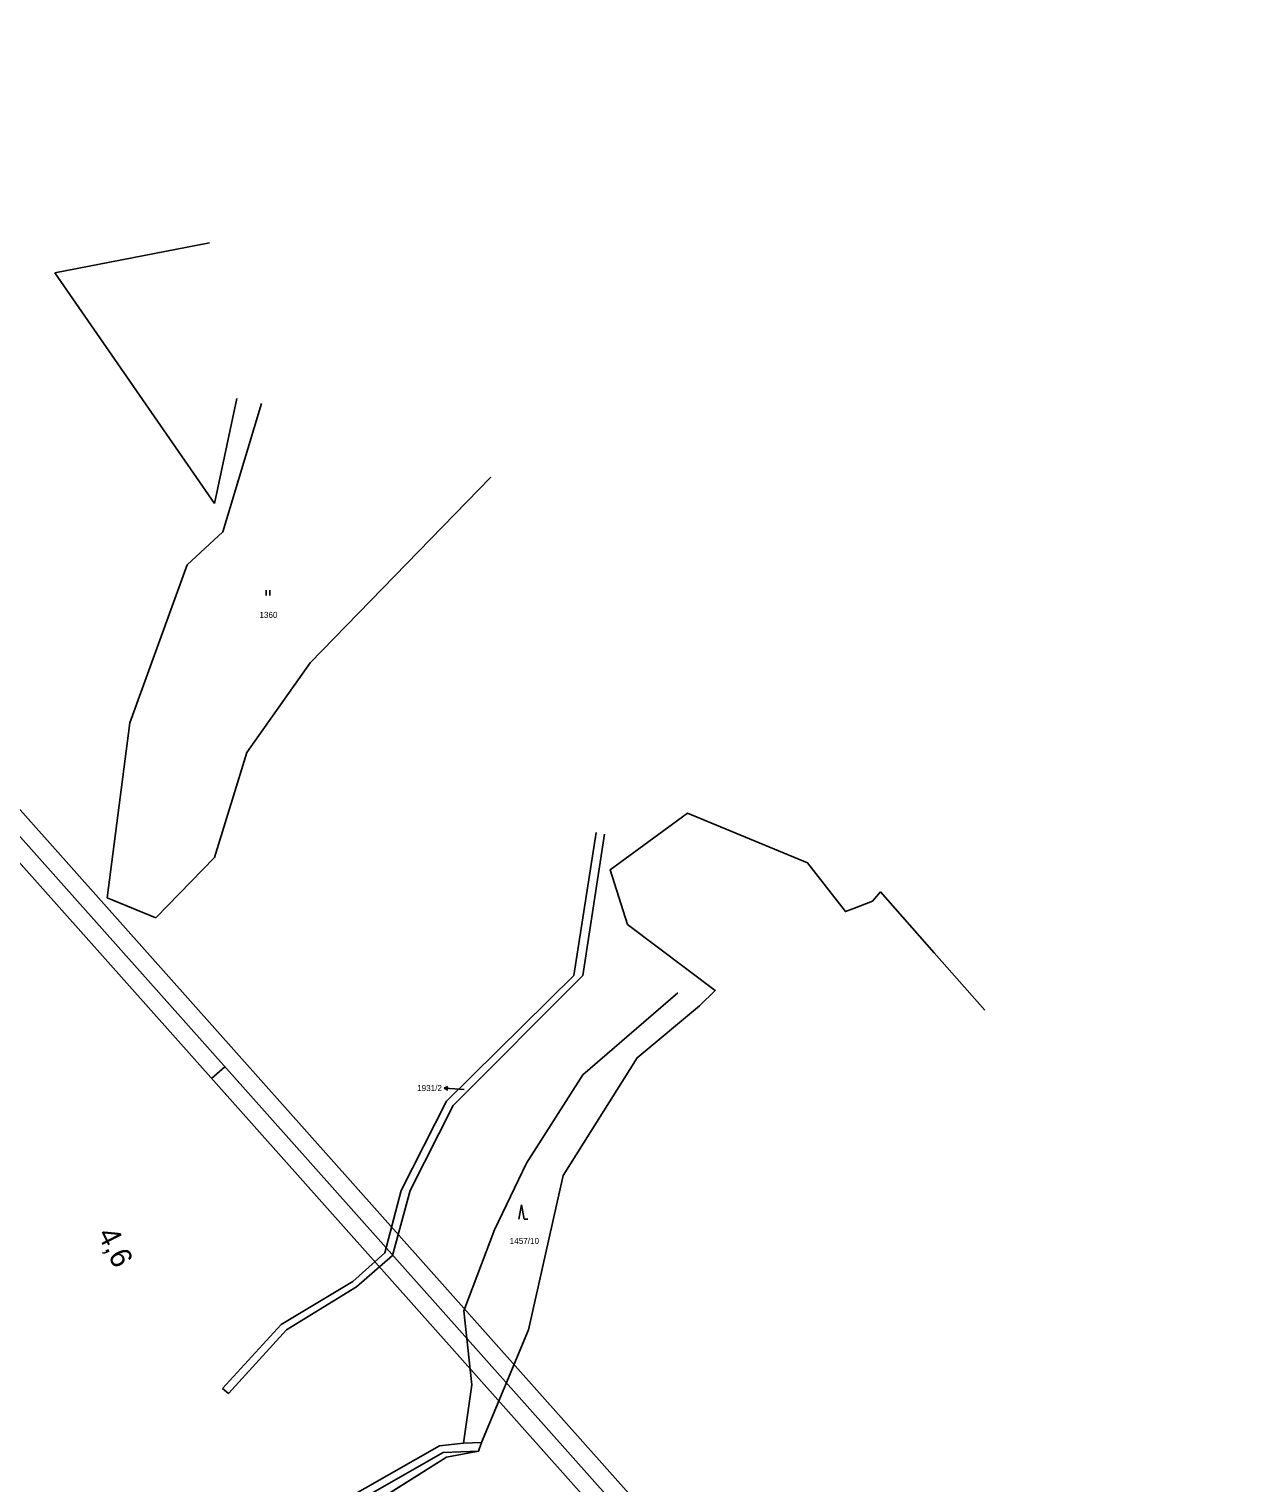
# Model space of a CAD drawing. Extents: x -866656 to -858817, y -1041816 to -1038653.
# Drawn here: x -865010.9 to -864673, y -1040373 to -1039965.6 of the extents above; entities that cross this region are included whole.
import ezdxf

# ---------------------------------------------------------------- set-up
doc = ezdxf.new("R2010")
doc.units = 0
for name, color, linetype in [('Hranice parcel', 7, 'Continuous'), ('Parcelní čísla', 7, 'Continuous'), ('Polygon ku', 7, 'Continuous'), ('Pop  PČ popisy', 7, 'Continuous'), ('tisk ramy', 7, 'Continuous'), ('Vrstva 7', 7, 'Continuous'), ('Značky kultur', 7, 'Continuous')]:
    doc.layers.add(name, color=color, linetype=linetype)

msp = doc.modelspace()

# ---------------------------------------------------------------- linework, layer by layer
at = {"layer": 'Hranice parcel'}
for p, q in [((-864960.28, -1040025.5), (-865003.64, -1040033.94)), ((-865003.64, -1040033.94), (-864958.88, -1040098.54)), ((-864958.88, -1040098.54), (-864952.62, -1040069.15)), ((-864956.54, -1040106.53), (-864945.76, -1040070.56)), ((-864881.51, -1040091.15), (-864932.05, -1040143.17)), ((-864966.57, -1040115.79), (-864956.54, -1040106.53)), ((-864982.65, -1040160.02), (-864966.57, -1040115.79)), ((-864932.05, -1040143.17), (-864949.88, -1040168.33)), ((-864989.01, -1040209.06), (-864982.65, -1040160.02)), ((-864949.88, -1040168.33), (-864958.94, -1040197.78)), ((-864852, -1040190.74), (-864858.23, -1040230.86)), ((-864855.69, -1040230.8), (-864849.66, -1040191.21)), ((-864958.94, -1040197.78), (-864975.36, -1040214.7)), ((-864975.36, -1040214.7), (-864989.01, -1040209.06)), ((-864892.07, -1040267.21), (-864855.69, -1040230.8)), ((-864858.23, -1040230.86), (-864893.89, -1040266)), ((-864855.68, -1040258.63), (-864829.05, -1040235.69)), ((-864840.47, -1040253.86), (-864823.05, -1040239.37)), ((-864861.25, -1040286.85), (-864840.47, -1040253.86)), ((-864871.44, -1040283.43), (-864855.68, -1040258.63)), ((-864893.89, -1040266), (-864906.61, -1040291.09)), ((-864904.04, -1040291.1), (-864892.07, -1040267.21)), ((-864880.43, -1040302.05), (-864871.44, -1040283.43)), ((-864870.94, -1040330.15), (-864861.25, -1040286.85)), ((-864906.61, -1040291.09), (-864911.13, -1040308.53)), ((-864908.98, -1040309.25), (-864904.04, -1040291.1)), ((-864888.99, -1040324.76), (-864880.43, -1040302.05)), ((-864911.13, -1040308.53), (-864920.12, -1040316.54)), ((-864919.1, -1040318.02), (-864908.98, -1040309.25)), ((-864920.12, -1040316.54), (-864940.25, -1040328.64)), ((-864938.71, -1040330.09), (-864919.1, -1040318.02)), ((-864886.78, -1040345.49), (-864888.99, -1040324.76)), ((-864940.25, -1040328.64), (-864956.69, -1040346.6)), ((-864954.99, -1040347.98), (-864938.71, -1040330.09)), ((-864884.09, -1040361.7), (-864870.94, -1040330.15)), ((-864956.69, -1040346.6), (-864954.99, -1040347.98)), ((-864889.09, -1040361.91), (-864886.78, -1040345.49)), ((-864895.84, -1040362.62), (-864947.33, -1040391.83)), ((-864894.83, -1040364.45), (-864946.61, -1040393.97)), ((-864889.09, -1040361.91), (-864895.84, -1040362.62)), ((-864884.92, -1040364.12), (-864894.83, -1040364.45)), ((-864893.92, -1040365.81), (-864884.92, -1040364.12)), ((-864884.09, -1040361.7), (-864889.09, -1040361.91)), ((-864884.92, -1040364.12), (-864884.09, -1040361.7)), ((-864939.01, -1040394.23), (-864893.92, -1040365.81))]:
    msp.add_line(p, q, dxfattribs=at)
at = {"layer": 'Polygon ku'}
msp.add_lwpolyline([(-864939.01, -1040394.23), (-864893.92, -1040365.81), (-864884.92, -1040364.12), (-864884.09, -1040361.7), (-864870.94, -1040330.15), (-864861.25, -1040286.85), (-864840.47, -1040253.86), (-864823.05, -1040239.37), (-864818.58, -1040235.05), (-864843.21, -1040216.53), (-864848.05, -1040201.18), (-864826.36, -1040185.34), (-864792.74, -1040199.25), (-864782.14, -1040212.93), (-864779.55, -1040211.92), (-864774.54, -1040209.96), (-864772.25, -1040207.39), (-864757.22, -1040224.45), (-864743.01, -1040240.58)], dxfattribs=at)
at = {"layer": 'Pop  PČ popisy'}
for p, q in [((-864894.51, -1040262.36), (-864893.48, -1040261.93)), ((-864891.52, -1040262.57), (-864894.51, -1040262.36)), ((-864894.51, -1040262.36), (-864893.55, -1040262.93)), ((-864888.97, -1040262.74), (-864891.52, -1040262.57))]:
    msp.add_line(p, q, dxfattribs=at)
at = {"layer": 'tisk ramy'}
msp.add_line((-864959.72, -1040259.7), (-864955.99, -1040256.38), dxfattribs=at)
for points in [[(-865732.63, -1039823.16), (-864894.8, -1040764.23), (-864672.98, -1040566.75), (-865510.81, -1039625.68)], [(-865511.22, -1039632.74), (-864680.04, -1040566.34), (-864894.39, -1040757.18), (-865725.57, -1039823.57)], [(-865718.52, -1039823.98), (-865030.3, -1040597.01), (-864823.41, -1040412.82), (-865511.63, -1039639.79)], [(-865511.63, -1039639.79), (-864823.41, -1040412.82), (-865030.3, -1040597.01), (-865718.52, -1039823.98)]]:
    msp.add_lwpolyline(points, close=True, dxfattribs=at)
at = {"layer": 'Značky kultur'}
for p, q in [((-864944.39, -1040124.36), (-864944.39, -1040122.86)), ((-864943.39, -1040124.36), (-864943.39, -1040122.86)), ((-864872.84, -1040295.1), (-864873.59, -1040299.1)), ((-864872.09, -1040299.1), (-864872.84, -1040295.1)), ((-864872.09, -1040299.1), (-864871.09, -1040299.1))]:
    msp.add_line(p, q, dxfattribs=at)

# ---------------------------------------------------------------- texts
at = {"layer": 'Parcelní čísla'}
for s, p in [('1360', (-864946.31, -1040130.63)), ('1931/2', (-864902.12, -1040263.21)), ('1457/10', (-864876.18, -1040306.05))]:
    msp.add_text(s, height=1.7, dxfattribs=at).set_placement(p)
at = {"layer": 'Vrstva 7'}
msp.add_text('4,6', height=6, rotation=296.5945, dxfattribs=at).set_placement((-864991.81, -1040303.25))

doc.saveas('drawing.dxf')
